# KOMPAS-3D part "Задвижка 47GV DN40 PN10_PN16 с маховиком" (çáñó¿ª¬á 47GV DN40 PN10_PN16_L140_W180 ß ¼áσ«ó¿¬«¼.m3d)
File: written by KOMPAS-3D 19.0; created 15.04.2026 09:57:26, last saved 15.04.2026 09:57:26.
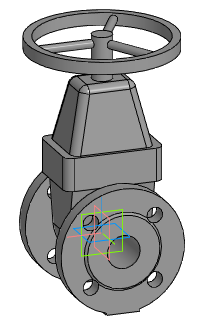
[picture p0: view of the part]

Document properties: Автор: Евгений; Полное имя файла: Z:\3.Личные\kachalov\3d для проектировщиков\2.1 Тип 47GV, 47GV.Z\Задвижка 47GV_DN40-DN600\stp_Задвижка 47GV\Задвижка 47GV DN40 PN10_PN16_L140_W180 с маховиком.m3d

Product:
- Part/product: Задвижка 47GV DN40 PN10_PN16 с маховиком

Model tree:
1. Операция без истории:1  (labels: Задвижка 47GV DN40 PN10_PN16 с маховиком)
